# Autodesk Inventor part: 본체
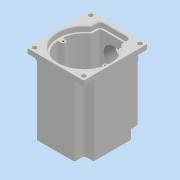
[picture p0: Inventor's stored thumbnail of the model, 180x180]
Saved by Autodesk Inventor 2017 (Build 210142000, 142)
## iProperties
Part Number: 본체
Material: 일반
Document SubType Name: Modeling
Designer: MRC
Density: 1 g/cm^3
Appearance: 기본값
Author: MRC
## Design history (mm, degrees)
sketch "스케치4"
  geometry: L1 (49, -55)-(-49, -55); L2 (-49, -55)-(-49, 55); L3 (-49, 55)-(49, 55); L4 (49, 55)-(49, -55); L5 (49, -55)-(-49, 55); L6 (-49, -55)-(49, 55); 1 further point
  constraints: 12 end point, 2 midpoint, 2 parallel, 1 horizontal, 1 perpendicular
  dimensions: "d6" = 98 distance of L2.end L3.end; "d7" = 110 distance of L1.end L2.end
extrude "돌출2" new body sketch "스케치4" distance "d8" = 130; taper "d9" = 0 deg
node "작업 평면1"
sketch "스케치6"
  geometry: L1 (-33, 28)-(-49, 28); L2 (-49, 28)-(-49, 55); L3 (-49, 55)-(-33, 55); L4 (-33, 55)-(-33, 28); L5 (-49, 55)-(49, 55) reference; L6 (-49, -55)-(-49, 55) reference; 1 further point
  constraints: 8 end point, 2 parallel, 1 horizontal, 1 perpendicular
  dimensions: "d11" = 16 distance of L2.end L3.end; "d12" = 27 distance of L2.end L1.end
extrude "돌출3" cut sketch "스케치6" stored distance "d13" = 10; taper "d14" = 0 deg
sketch "스케치12"
  geometry: L1 (-49, -55)-(49, -55) reference; L2 (-49, 55)-(-49, -55) reference; L3 (49, -55)-(49, 55) reference; L4 (49, 55)-(-49, 55) reference; L5 (-23, 30.143)-(-23, 45); L6 (-23, 45)-(23, 45); L7 (23, 45)-(23, 30.143); L8 (26, 48)-(-26, 48); L9 (-26, 48)-(-26, 31.729); L10 (26, 31.729)-(26, 48); A1 r 42 centre (0, -5) between (-23, 30.143) and (23, 30.143); A2 r 45 centre (0, -5) between (-26, 31.729) and (26, 31.729); 3 further points
  constraints: 12 end point, 4 point on circle, 2 centre point, 2 coincident, 2 parallel, 2 vertical alignment, 1 midpoint, 3 other
  dimensions: "d20" = 84 diameter of A1; "d21" = 50 distance from line of L1 A1.centre; "d23" = 46 distance of L5.end L6.end; "d25" = 23 horizontal distance of point (0, 0) L5.start; "d26" = 50 distance from line of A1.centre L6; "d27" = 23 horizontal distance of point (0, 0) L7.end; "d28" = 3 distance between parallel lines of L6 L8
extrude "돌출5" cut sketch "스케치12" distance "d29" = 121; taper "d30" = 0 deg
extrude "돌출6" cut sketch "스케치12" distance "d31" = 9; taper "d32" = 0 deg
node "작업 평면2"
sketch "스케치16"
  geometry: L1 (-33, -55)-(-49, -55); L2 (-49, -55)-(-49, -38); L3 (-49, -38)-(-33, -38); L4 (-33, -38)-(-33, -55); 2 further points
  constraints: 8 end point, 2 parallel, 1 coincident, 1 horizontal, 1 perpendicular
  dimensions: "d34" = 17 distance of L1.end L2.end; "d35" = 16 distance of L2.end L3.end
extrude "돌출7" cut sketch "스케치16" stored distance "d36" = 3; taper "d37" = 0 deg
fillet "모깎기1" dims "d38" = 6
fillet "모깎기2" dims "d39" = 3
fillet "모깎기3" dims "d40" = 3
fillet "모깎기4" dims "d41" = 3
fillet "모깎기5" dims "d42" = 6
sketch "스케치20"
  geometry: L1 (-49, 28)-(-33, 28) reference; L2 (-49, -38)-(-49, 28) reference; L3 (-33, -38)-(-49, -38) reference; L4 (33, -55)-(-33, -55) reference; L5 (33, -38)-(33, -55) reference; L6 (49, -38)-(33, -38) reference; L7 (49, 28)-(49, -38) reference; L8 (33, 28)-(49, 28) reference; L9 (-33, 55)-(33, 55) reference; L10 (-33, 28)-(-33, 55) reference; L11 (33, 55)-(33, 28) reference; L12 (-49, -5)-(49, -5); A1 r 15 centre (0, -25) between (-8.978, -12.984) and (8.978, -12.984); A2 r 21 centre (0, 6) between (8.978, -12.984) and (-8.978, -12.984); 1 further point
  constraints: 4 point on circle, 2 centre point, 2 end point, 2 midpoint, 2 vertical alignment, 1 horizontal
  dimensions: "d44" = 30 diameter of A1; "d46" = 42 diameter of A2; "d47" = 50 distance between parallel lines of L4 L12; "d48" = 20 distance from line of L12 A1.centre; "d49" = 11 distance from line of A2.centre L12
extrude "돌출8" join sketch "스케치20" distance "d50" = 7; taper "d51" = 0 deg
sketch "스케치23"
  geometry: L1 (27, -21)-(-27, -21); L2 (-27, -21)-(-27, 33); L3 (-27, 33)-(27, 33); L4 (27, 33)-(27, -21); L5 (33, 55)-(-33, 55) reference; L6 (-33, -55)-(33, -55) reference; 3 further points
  constraints: 8 end point, 2 midpoint, 2 parallel, 1 horizontal, 1 perpendicular, 1 vertical alignment
  dimensions: "d53" = 54 distance of L2.end L3.end; "d54" = 54 distance of L1.end L2.end; "d55" = 88 distance between parallel lines of L3 L6
extrude "돌출9" join sketch "스케치23" distance "d56" = 7; taper "d57" = 0 deg
sketch "스케치25"
  geometry: C1 r 11 at (0, -25); A1 r 15 centre (0, -25) between (-8.978, -12.984) and (8.978, -12.984) reference; 1 further point
  constraints: 1 centre point, 1 coincident
  dimensions: "d66" = 22 diameter of C1
extrude "돌출11" cut sketch "스케치25" distance "d67" = 7; taper "d68" = 0 deg
sketch "스케치26"
  geometry: C1 r 11 at (0, 0) reference; C2 r 9.5 at (0, 0); 1 further point
  constraints: 1 centre point, 1 coincident
  dimensions: "d70" = 19 diameter of C2
extrude "돌출12" cut sketch "스케치26" distance "d71" = 3; taper "d72" = 0 deg
sketch "스케치27"
  geometry: C1 r 17.5 at (0, 6); A1 r 21 centre (0, 6) between (8.978, -12.984) and (-8.978, -12.984) reference; 1 further point
  constraints: 1 centre point, 1 coincident
  dimensions: "d73" = 35 diameter of C1
extrude "돌출13" cut sketch "스케치27" distance "d74" = 10; taper "d75" = 0 deg
sketch "스케치28"
  geometry: C1 r 17.5 at (0, 0) reference; C2 r 14 at (0, 0); 1 further point
  constraints: 1 centre point, 1 coincident
  dimensions: "d76" = 28 diameter of C2
extrude "돌출14" cut sketch "스케치28" stored distance "d77" = 10; taper "d78" = 0 deg
sketch "스케치29"
  geometry: C1 r 14 at (0, 6) reference; C2 r 16 at (0, 6); 1 further point
  constraints: 1 centre point, 1 coincident
  dimensions: "d79" = 32 diameter of C2
extrude "돌출15" cut sketch "스케치29" distance "d80" = 8.3; taper "d81" = 0 deg
sketch "스케치30"
  geometry: L1 (98, 0)-(0, 0) reference; C1 r 15 at (49, 89); 2 further points
  constraints: 1 centre point, 1 midpoint, 1 vertical alignment
  dimensions: "d82" = 30 diameter of C1; "d83" = 89 distance from line of C1.centre L1
extrude "돌출16" join sketch "스케치30" distance "d84" = 5; taper "d85" = 0 deg
sketch "스케치31"
  geometry: L1 (16, 130)-(82, 130) reference; L2 (98, 0)-(0, 0) reference; C1 r 22.5 at (49, 40); 2 further points
  constraints: 1 centre point, 1 midpoint, 1 vertical alignment
  dimensions: "d86" = 45 diameter of C1; "d87" = 40 distance from line of L2 C1.centre
extrude "돌출17" join sketch "스케치31" distance "d88" = 10; taper "d89" = 0 deg
sketch "스케치32"
  geometry: C1 r 15 at (0, 0) reference; C2 r 10 at (0, 0); 1 further point
  constraints: 1 centre point, 1 coincident
  dimensions: "d90" = 20 diameter of C2
extrude "돌출18" cut sketch "스케치32" stored distance "d91" = 10; taper "d92" = 0 deg
sketch "스케치33"
  geometry: C1 r 10 at (20, -80) reference; C2 r 15 at (20, -80); 1 further point
  constraints: 1 centre point, 1 coincident
  dimensions: "d93" = 30 diameter of C2
extrude "돌출19" cut sketch "스케치33" distance "d94" = 5; taper "d95" = 0 deg
hole "구멍1" diameter "d98" = 33.376; stored, may be unused: countersink angle "d102" = 90 deg, drill point angle "d104" = 118 deg; dims "d96" = 10, "d97" = 10, "d99" = 70, "d100" = 4, "d101" = 2, "d103" = 77.3
sketch "스케치35"
  geometry: L1 (-49, -55)-(49, -55) reference; L2 (-36, -5)-(36, -5); L3 (-35.777, -1)-(-41.809, -1); L4 (-35.777, -9)-(-41.809, -9); L5 (35.777, -1)-(41.809, -1); L6 (35.777, -9)-(41.809, -9); A1 r 36 centre (0, -5) between (-36, -5) and (36, -5); A2 r 4 centre (-36, -5) between (-36, -9) and (-36, -1); A3 r 4 centre (36, -5) between (36, -1) and (36, -9); A4 r 42 centre (0, -5) between (-25.375, 28.468) and (25.375, 28.468) reference; 1 further point
  constraints: 14 point on circle, 10 end point, 5 horizontal, 4 point on line, 4 tangent, 3 centre point, 2 coincident, 1 vertical alignment
  dimensions: "d105" = 72 diameter of A1; "d106" = 50 distance from line of L1 A1.centre; "d108" = 50 distance between parallel lines of L1 L2; "d109" = 8 diameter of A2; "d110" = 8 diameter of A3
extrude "돌출20" join sketch "스케치35" stored distance "d111" = 105; taper "d112" = 0 deg
sketch "스케치36"
  geometry: A1 r 4 centre (-36, -5) between (-36, -9) and (-36, -1) reference; A2 r 4 centre (36, -5) between (36, -1) and (36, -9) reference; 3 further points
  constraints: 2 coincident
hole "구멍2" sketch "스케치36" at (36, -5), (-36, -5) diameter "d113" = 3.242; stored, may be unused: countersink angle "d117" = 90 deg, drill point angle "d119" = 118 deg; dims "d114" = 7, "d115" = 4, "d116" = 2, "d118" = 9
fillet "모깎기6" dims "d120" = 3
fillet "모깎기7" dims "d121" = 0.3
chamfer "모따기1" distance "d122" = 1; stored, may be unused: second distance "d123" = 2, angle "d124" = 45 deg
chamfer "모따기2" distance "d125" = 1; stored, may be unused: second distance "d126" = 2, angle "d127" = 45 deg
chamfer "모따기3" distance "d128" = 1; stored, may be unused: second distance "d129" = 2, angle "d130" = 45 deg
fillet "모깎기8" dims "d131" = 3
fillet "모깎기9" dims "d132" = 3
fillet "모깎기10" dims "d133" = 3
fillet "모깎기11" dims "d134" = 3
fillet "모깎기12" dims "d135" = 3
fillet "모깎기13" dims "d136" = 3
fillet "모깎기14" dims "d137" = 3
fillet "모깎기15" dims "d138" = 3
fillet "모깎기16" dims "d139" = 3
chamfer "모따기4" distance "d140" = 1; stored, may be unused: second distance "d141" = 2, angle "d142" = 45 deg
sketch "스케치38"
  geometry: C1 r 3.5 at (-42, 48); 1 further point
  constraints: 1 centre point
  dimensions: "d143" = 7 diameter of C1; "d144" = 42 horizontal distance of point (0, 0) C1.centre; "d145" = 48 vertical distance of point (0, 0) C1.centre
extrude "돌출21" cut sketch "스케치38" stored distance "d146" = 105; taper "d147" = 0 deg
fillet "모깎기17" dims "d148" = 3
fillet "모깎기18" dims "d149" = 3
fillet "모깎기19" dims "d150" = 0.3
fillet "모깎기20" dims "d151" = 0.3
sketch "스케치43"
  geometry: L1 (-130, 104)-(-130, 83) reference; L2 (-13, 107)-(-127, 107) reference; 2 further points
  constraints: 1 other
  dimensions: "d152" = 65 distance from line of point (-65, 47) L1; "d153" = 60 distance from line of point (-65, 47) L2
feature "엠보싱1" sketch "스케치43" dims "d154" = 0.5, "d155" = 0
node "솔리드2"
mirror "미러1"
mirror "미러3"
mirror "미러4"
mirror "미러5"
